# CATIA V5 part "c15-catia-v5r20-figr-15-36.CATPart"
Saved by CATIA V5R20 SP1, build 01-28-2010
Part number: Part1
Bounding box of the stored display mesh (mm): x -63.331 to 107.433, y -39.139 to 39.139, z 0 to 70.926
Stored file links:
  D:\v5_r20\psrt_files_downloaded\c15\c15-catia-v5r20-figr-15-36.CATPart
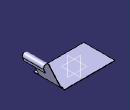
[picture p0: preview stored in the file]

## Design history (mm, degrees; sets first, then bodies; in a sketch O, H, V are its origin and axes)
SheetMetalParameters1: Thickness 1, BendRadius 2, KFactor 0.400515 {= log(min(100,max(20*SheetMetalParameters1.BendRadius,SheetMetalParameters1.Thickness)/SheetMetalParameters1.Thickness))/log(100)/2}, ReliefRadialLength 1, ReliefAxialLength 2, MinimumBendRadius 0
Body1 (main body)
  Sketch1 on xy-plane, origin (0, 0, 0), H (1, 0, 0), V (0, 1, 0)
    line L1 (-63.3311, 39.1393) -> (63.3311, 39.1393)
    line L2 (63.3311, 39.1393) -> (63.3311, -39.1393)
    line L3 (63.3311, -39.1393) -> (-63.3311, -39.1393)
    line L4 (-63.3311, -39.1393) -> (-63.3311, 39.1393)
    horizontal: L1 H, L3 H
    vertical: L2 V, L4 V
    symmetry: L4 L2 V, L1 L3 H
  Wall1: Thickness 1, Profile Sketch1
  d_NewWallOnEdge1: NewWallOnEdge_Edge edge [face of Wall1 | face of Wall1], NewWallOnEdge_Length 67, NewWallOnEdge_HeightLimitOffset 0, NewWallOnEdge_WidthOffset1 -16, NewWallOnEdge_WidthOffset2 -9, NewWallOnEdge_Angle 115, NewWallOnEdge_BendRadiusValue 2 {= SheetMetalParameters1.BendRadius}, NewWallOnEdge_BendTable SheetMetalParameters1, KFacteur 0.400515 {= log(min(100,max(20*d_NewWallOnEdge1.Radius,SheetMetalParameters1.Thickness)/SheetMetalParameters1.Thickness))/log(100)/2}
  Flange1: Angle 4, Length 10, Radius 6, KFacteur 0.5 {= log(min(100,max(20*Flange1.Radius,SheetMetalParameters1.Thickness)/SheetMetalParameters1.Thickness))/log(100)/2}, Guide edge [face of d_NewWallOnEdge1 | face of d_NewWallOnEdge1]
